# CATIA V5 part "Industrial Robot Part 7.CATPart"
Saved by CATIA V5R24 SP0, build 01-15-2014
Part number: Industrial Robot Part 7
Source: Unknown
Material "Crisp Orange": density 7860 kg/m3, Young's modulus 2e+11 Pa, Poisson ratio 0.266
Bounding box of the stored display mesh (mm): x -232.329 to 136.416, y -188.522 to 103.133, z -172.848 to 152.441
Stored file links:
  C:\Users\cdl\Downloads\2024_CAD_final\p2\Industrial Robot Part 7.CATPart
  D:\Program Files\Dassault Systemes\B24\win_b64\startup\materials\Catalog.CATMaterial
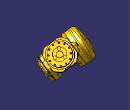
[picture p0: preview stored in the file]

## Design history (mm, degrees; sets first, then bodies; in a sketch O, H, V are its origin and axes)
Body1 (main body), material "Crisp Orange"
  Solid1 "Solid 1": solid without history
  Translate1: Direction (0, 0, 1), Length -1683, ToTransfor Solid1
  Translate2: Direction (1, 0, 0), Length -1638, ToTransfor Translate1
  Translate3: Direction (0, 0, 1), Length -71, ToTransfor Translate2
  Rotate1: Axis X axis, Angle 219, ToTransfor Translate3
  Rotate2: Axis Y axis, Angle 219, ToTransfor Rotate1
  Rotate3: Axis Z axis, Angle 219, ToTransfor Rotate2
